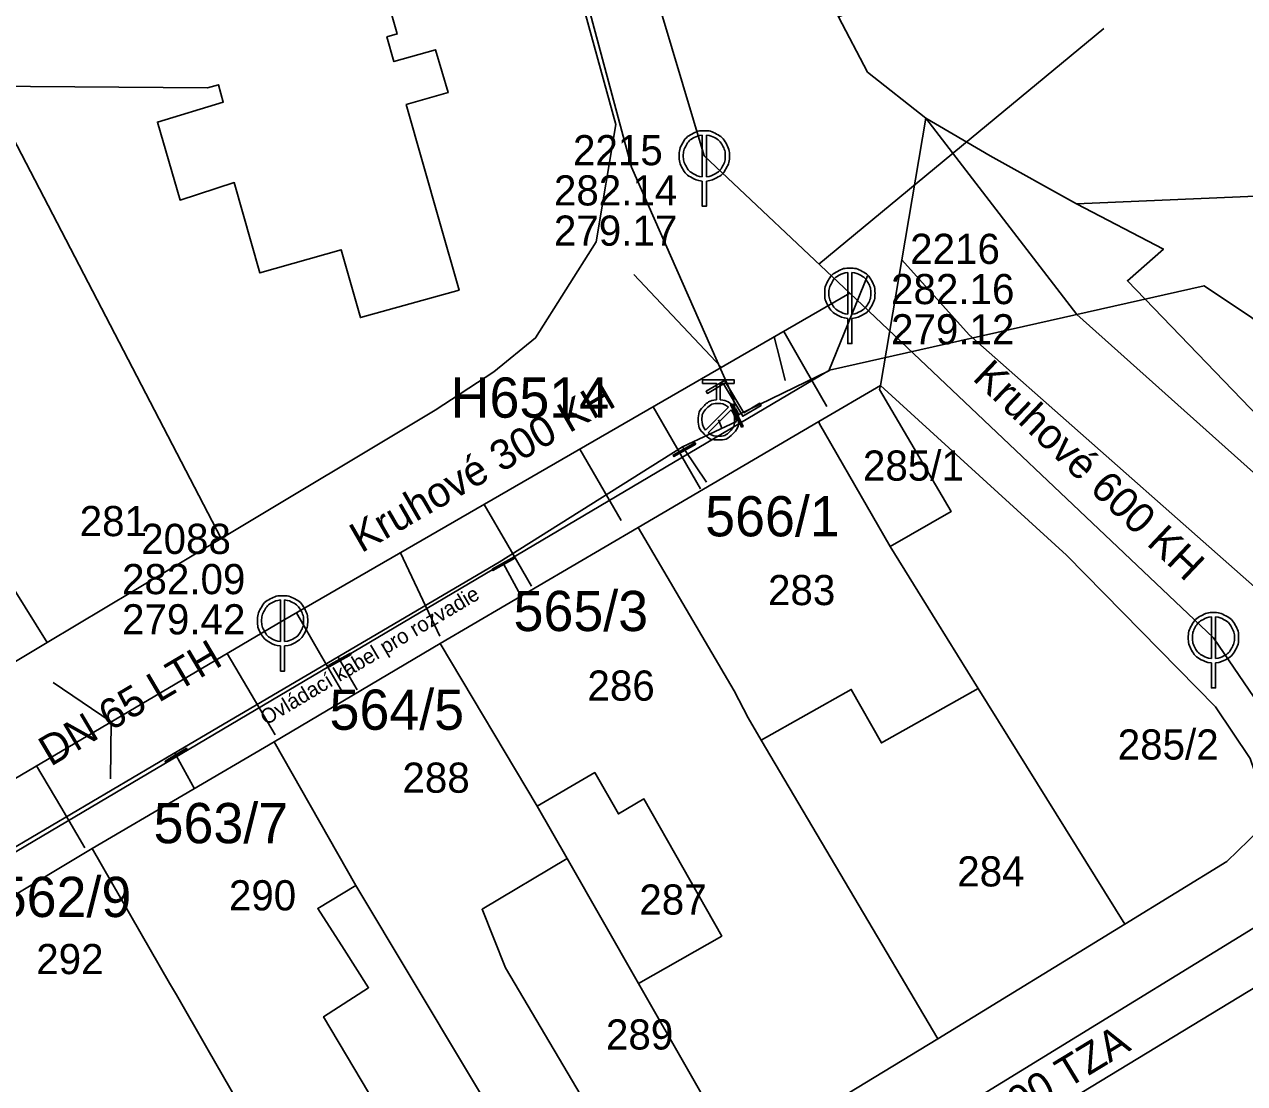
# Model space of a CAD drawing. Extents: x -571312 to -571060, y -1087128 to -1086933.
# Drawn here: x -571153.9 to -571093.3, y -1087034.1 to -1086981.5 of the extents above; entities that cross this region are included whole.
import ezdxf

# ---------------------------------------------------------------- set-up
doc = ezdxf.new("R2010")
doc.units = 0
for name, color, linetype in [('Adresní místo-text', 7, 'Continuous'), ('Armatura vodovodní', 7, 'Continuous'), ('Default', 7, 'Continuous'), ('Elektro NN - vedení', 7, 'Continuous'), ('Elektro VN_ VVN - popis', 7, 'Continuous'), ('Hydrant', 7, 'Continuous'), ('Kanalizační přípojka', 7, 'Continuous'), ('Kanalizační stoka', 7, 'Continuous'), ('Kanalizační šachta', 7, 'Continuous'), ('Označení hydrantu', 7, 'Continuous'), ('Parcela-polygon', 7, 'Continuous'), ('Parcela-text', 7, 'Continuous'), ('Popis kmenové stoky', 7, 'Continuous'), ('Popis šachty', 7, 'Continuous'), ('Vodovodní přípojka', 7, 'Continuous'), ('Vodovodní řad', 7, 'Continuous'), ('Změna materiálu', 7, 'Continuous'), ('Řad vodovodní popis', 7, 'Continuous')]:
    doc.layers.add(name, color=color, linetype=linetype)

msp = doc.modelspace()

# ---------------------------------------------------------------- linework, layer by layer
at = {"layer": 'Armatura vodovodní'}
for points in [[(-571118.748, -1087000.329), (-571118.201, -1087001.453), (-571118.272, -1087001.488), (-571118.818, -1087000.363), (-571118.748, -1087000.329)], [(-571120.555, -1087002.333), (-571121.642, -1087002.95), (-571121.681, -1087002.882), (-571120.594, -1087002.265), (-571120.555, -1087002.333)], [(-571129.55, -1087008.003), (-571130.637, -1087008.62), (-571130.676, -1087008.552), (-571129.588, -1087007.935), (-571129.55, -1087008.003)], [(-571137.685, -1087012.803), (-571138.78, -1087013.406), (-571138.818, -1087013.337), (-571137.723, -1087012.734), (-571137.685, -1087012.803)], [(-571145.837, -1087017.527), (-571146.906, -1087018.174), (-571146.946, -1087018.107), (-571145.877, -1087017.46), (-571145.837, -1087017.527)]]:
    msp.add_lwpolyline(points, dxfattribs=at)
at = {"layer": 'Default'}
for points in [[(-571120.233, -1086989.248), (-571120.491, -1086989.23), (-571120.753, -1086989.084), (-571121.05, -1086988.92), (-571121.215, -1086988.623), (-571121.38, -1086988.325), (-571121.38, -1086988), (-571121.38, -1086987.673), (-571121.212, -1086987.373), (-571121.043, -1086987.072), (-571120.745, -1086986.911), (-571120.447, -1086986.75), (-571120.13, -1086986.75), (-571119.815, -1086986.75), (-571119.516, -1086986.911), (-571119.217, -1086987.072), (-571119.048, -1086987.373), (-571118.88, -1086987.673), (-571118.88, -1086988), (-571118.88, -1086988.325), (-571119.045, -1086988.623), (-571119.21, -1086988.92), (-571119.507, -1086989.084), (-571119.769, -1086989.23), (-571120.027, -1086989.248)], [(-571120.233, -1086986.962), (-571120.43, -1086986.979), (-571120.645, -1086987.094), (-571120.894, -1086987.229), (-571121.033, -1086987.479), (-571121.172, -1086987.729), (-571121.172, -1086988), (-571121.172, -1086988.271), (-571121.036, -1086988.518), (-571120.899, -1086988.764), (-571120.65, -1086988.901), (-571120.438, -1086989.021), (-571120.233, -1086989.035)], [(-571120.027, -1086989.035), (-571119.822, -1086989.021), (-571119.608, -1086988.901), (-571119.361, -1086988.764), (-571119.224, -1086988.518), (-571119.088, -1086988.271), (-571119.088, -1086988), (-571119.088, -1086987.729), (-571119.228, -1086987.479), (-571119.368, -1086987.229), (-571119.617, -1086987.094), (-571119.83, -1086986.979), (-571120.027, -1086986.962)], [(-571112.993, -1086996.078), (-571113.251, -1086996.06), (-571113.513, -1086995.914), (-571113.81, -1086995.75), (-571113.975, -1086995.453), (-571114.14, -1086995.155), (-571114.14, -1086994.83), (-571114.14, -1086994.503), (-571113.972, -1086994.203), (-571113.803, -1086993.902), (-571113.505, -1086993.741), (-571113.207, -1086993.58), (-571112.89, -1086993.58), (-571112.575, -1086993.58), (-571112.276, -1086993.741), (-571111.977, -1086993.902), (-571111.808, -1086994.203), (-571111.64, -1086994.503), (-571111.64, -1086994.83), (-571111.64, -1086995.155), (-571111.805, -1086995.453), (-571111.97, -1086995.75), (-571112.267, -1086995.914), (-571112.529, -1086996.06), (-571112.787, -1086996.078)], [(-571112.993, -1086993.792), (-571113.19, -1086993.809), (-571113.405, -1086993.924), (-571113.654, -1086994.059), (-571113.793, -1086994.309), (-571113.932, -1086994.559), (-571113.932, -1086994.83), (-571113.932, -1086995.101), (-571113.796, -1086995.348), (-571113.659, -1086995.594), (-571113.41, -1086995.731), (-571113.198, -1086995.851), (-571112.993, -1086995.865)], [(-571112.787, -1086995.865), (-571112.582, -1086995.851), (-571112.368, -1086995.731), (-571112.121, -1086995.594), (-571111.984, -1086995.348), (-571111.848, -1086995.101), (-571111.848, -1086994.83), (-571111.848, -1086994.559), (-571111.988, -1086994.309), (-571112.128, -1086994.059), (-571112.377, -1086993.924), (-571112.59, -1086993.809), (-571112.787, -1086993.792)], [(-571119.336, -1087000.132), (-571118.978, -1087000.161), (-571118.72, -1087000.421), (-571118.429, -1087000.714), (-571118.429, -1087001.13), (-571118.429, -1087001.544), (-571118.722, -1087001.836), (-571119.015, -1087002.128), (-571119.431, -1087002.128), (-571119.844, -1087002.128), (-571120.137, -1087001.836), (-571120.429, -1087001.544), (-571120.429, -1087001.13), (-571120.429, -1087000.714), (-571120.138, -1087000.421), (-571119.881, -1087000.159), (-571119.523, -1087000.132)], [(-571118.924, -1087000.489), (-571119.14, -1087000.314), (-571119.431, -1087000.314), (-571119.769, -1087000.314), (-571120.007, -1087000.551), (-571120.244, -1087000.788), (-571120.244, -1087001.126), (-571120.244, -1087001.417), (-571120.068, -1087001.634)], [(-571119.935, -1087001.767), (-571119.72, -1087001.939), (-571119.431, -1087001.939), (-571119.095, -1087001.939), (-571118.857, -1087001.701), (-571118.619, -1087001.464), (-571118.619, -1087001.126), (-571118.619, -1087000.837), (-571118.791, -1087000.622)], [(-571141.203, -1087012.368), (-571141.461, -1087012.35), (-571141.723, -1087012.204), (-571142.02, -1087012.04), (-571142.185, -1087011.743), (-571142.35, -1087011.445), (-571142.35, -1087011.12), (-571142.35, -1087010.793), (-571142.182, -1087010.493), (-571142.013, -1087010.192), (-571141.715, -1087010.031), (-571141.417, -1087009.87), (-571141.1, -1087009.87), (-571140.785, -1087009.87), (-571140.486, -1087010.031), (-571140.187, -1087010.192), (-571140.018, -1087010.493), (-571139.85, -1087010.793), (-571139.85, -1087011.12), (-571139.85, -1087011.445), (-571140.015, -1087011.743), (-571140.18, -1087012.04), (-571140.477, -1087012.204), (-571140.739, -1087012.35), (-571140.997, -1087012.368)], [(-571141.203, -1087010.082), (-571141.4, -1087010.099), (-571141.615, -1087010.214), (-571141.864, -1087010.349), (-571142.003, -1087010.599), (-571142.142, -1087010.849), (-571142.142, -1087011.12), (-571142.142, -1087011.391), (-571142.006, -1087011.638), (-571141.869, -1087011.884), (-571141.62, -1087012.021), (-571141.408, -1087012.141), (-571141.203, -1087012.155)], [(-571140.997, -1087012.155), (-571140.792, -1087012.141), (-571140.578, -1087012.021), (-571140.331, -1087011.884), (-571140.194, -1087011.638), (-571140.058, -1087011.391), (-571140.058, -1087011.12), (-571140.058, -1087010.849), (-571140.198, -1087010.599), (-571140.338, -1087010.349), (-571140.587, -1087010.214), (-571140.8, -1087010.099), (-571140.997, -1087010.082)], [(-571094.913, -1087013.208), (-571095.171, -1087013.19), (-571095.433, -1087013.044), (-571095.73, -1087012.88), (-571095.895, -1087012.583), (-571096.06, -1087012.285), (-571096.06, -1087011.96), (-571096.06, -1087011.633), (-571095.892, -1087011.333), (-571095.723, -1087011.032), (-571095.425, -1087010.871), (-571095.127, -1087010.71), (-571094.81, -1087010.71), (-571094.495, -1087010.71), (-571094.196, -1087010.871), (-571093.897, -1087011.032), (-571093.728, -1087011.333), (-571093.56, -1087011.633), (-571093.56, -1087011.96), (-571093.56, -1087012.285), (-571093.725, -1087012.583), (-571093.89, -1087012.88), (-571094.187, -1087013.044), (-571094.449, -1087013.19), (-571094.707, -1087013.208)], [(-571094.913, -1087010.922), (-571095.11, -1087010.939), (-571095.325, -1087011.054), (-571095.574, -1087011.189), (-571095.713, -1087011.439), (-571095.852, -1087011.689), (-571095.852, -1087011.96), (-571095.852, -1087012.231), (-571095.716, -1087012.478), (-571095.579, -1087012.724), (-571095.33, -1087012.861), (-571095.118, -1087012.981), (-571094.913, -1087012.995)], [(-571094.707, -1087012.995), (-571094.502, -1087012.981), (-571094.288, -1087012.861), (-571094.041, -1087012.724), (-571093.904, -1087012.478), (-571093.768, -1087012.231), (-571093.768, -1087011.96), (-571093.768, -1087011.689), (-571093.908, -1087011.439), (-571094.048, -1087011.189), (-571094.297, -1087011.054), (-571094.51, -1087010.939), (-571094.707, -1087010.922)]]:
    msp.add_open_spline(points, degree=3, dxfattribs=at)
at = {"layer": 'Elektro NN - vedení'}
msp.add_lwpolyline([(-571071.926, -1087014.396), (-571073.5, -1087015.707), (-571083.992, -1087003.116), (-571092.911, -1086996.034), (-571095.272, -1086994.46), (-571113.896, -1086998.657), (-571175.538, -1087035.118), (-571177.374, -1087030.659), (-571213.311, -1086976.361), (-571216.983, -1086969.541), (-571228.263, -1086944.884), (-571229.263, -1086941.883)], dxfattribs=at)
at = {"layer": 'Hydrant'}
for points in [[(-571119.523, -1087000.132), (-571119.523, -1086999.315), (-571120.211, -1086999.315), (-571120.211, -1086999.128), (-571118.648, -1086999.128), (-571118.648, -1086999.315), (-571119.336, -1086999.315), (-571119.336, -1087000.132)], [(-571120.068, -1087001.634), (-571118.924, -1087000.489)], [(-571118.791, -1087000.622), (-571119.935, -1087001.767)]]:
    msp.add_lwpolyline(points, dxfattribs=at)
at = {"layer": 'Kanalizační přípojka'}
for points in [[(-571100.26, -1086981.67), (-571107.346, -1086987.523), (-571114.431, -1086993.376)], [(-571123.64, -1086993.9), (-571121.46, -1086996.21), (-571119.28, -1086998.52)], [(-571114.031, -1087000.454), (-571115.106, -1086998.592), (-571116.181, -1086996.73)], [(-571116.1, -1086999.17), (-571116.378, -1086998.087), (-571116.657, -1086997.005)], [(-571120.326, -1087004.551), (-571121.501, -1087002.516), (-571122.676, -1087000.481)], [(-571124.263, -1087006.132), (-571125.288, -1087004.356), (-571126.313, -1087002.581)], [(-571128.726, -1087009.401), (-571129.901, -1087007.366), (-571131.076, -1087005.331)], [(-571133.275, -1087011.878), (-571134.253, -1087009.805), (-571135.232, -1087007.732)], [(-571138.107, -1087014.704), (-571139.257, -1087012.712), (-571140.407, -1087010.72)], [(-571141.468, -1087016.794), (-571142.662, -1087014.77), (-571143.856, -1087012.746)], [(-571152.5, -1087014.18), (-571149.617, -1087016.144)], [(-571149.65, -1087018.97), (-571149.617, -1087016.144)], [(-571150.93, -1087022.404), (-571152.13, -1087020.369), (-571153.331, -1087018.334)]]:
    msp.add_lwpolyline(points, dxfattribs=at)
at = {"layer": 'Kanalizační stoka'}
for points in [[(-571131.72, -1086949.28), (-571125.925, -1086968.64), (-571120.13, -1086988)], [(-571120.13, -1086988), (-571112.89, -1086994.83)], [(-571141.1, -1087011.12), (-571112.89, -1086994.83)], [(-571112.89, -1086994.83), (-571094.81, -1087011.96)], [(-571185.11, -1087037.08), (-571141.1, -1087011.12)], [(-571094.81, -1087011.96), (-571085.827, -1087025.142)], [(-571123.22, -1087047.86), (-571104.524, -1087036.501), (-571085.827, -1087025.142)]]:
    msp.add_lwpolyline(points, dxfattribs=at)
at = {"layer": 'Kanalizační šachta'}
for points in [[(-571120.233, -1086989.035), (-571120.233, -1086986.962)], [(-571120.027, -1086986.962), (-571120.027, -1086989.035)], [(-571120.027, -1086989.248), (-571120.027, -1086990.5), (-571120.233, -1086990.5), (-571120.233, -1086989.248)], [(-571112.993, -1086995.865), (-571112.993, -1086993.792)], [(-571112.787, -1086993.792), (-571112.787, -1086995.865)], [(-571112.787, -1086996.078), (-571112.787, -1086997.33), (-571112.993, -1086997.33), (-571112.993, -1086996.078)], [(-571141.203, -1087012.155), (-571141.203, -1087010.082)], [(-571140.997, -1087010.082), (-571140.997, -1087012.155)], [(-571094.913, -1087012.995), (-571094.913, -1087010.922)], [(-571094.707, -1087010.922), (-571094.707, -1087012.995)], [(-571140.997, -1087012.368), (-571140.997, -1087013.62), (-571141.203, -1087013.62), (-571141.203, -1087012.368)], [(-571094.707, -1087013.208), (-571094.707, -1087014.46), (-571094.913, -1087014.46), (-571094.913, -1087013.208)]]:
    msp.add_lwpolyline(points, dxfattribs=at)
at = {"layer": 'Parcela-polygon'}
for points in [[(-571122.956, -1086932.879), (-571124.19, -1086936.69), (-571140.74, -1086942.7), (-571140.64, -1086942.98), (-571137.75, -1086951.51), (-571135.94, -1086951.84), (-571132.79, -1086956.45), (-571124.52, -1086986.44), (-571125.5, -1086992.28), (-571128.52, -1086997.05), (-571130.59, -1086998.74), (-571133.51, -1087000.65), (-571144.15, -1087007.02), (-571152.8, -1087012.2), (-571165.57, -1087019.85)], [(-571159.39, -1087027.73), (-571150.57, -1087022.45), (-571141.52, -1087017.13), (-571133.26, -1087012.24), (-571123.41, -1087006.48), (-571114.43, -1087001.2), (-571111.37, -1086999.41), (-571110.31, -1086993.17), (-571109.12, -1086986.12), (-571112.01, -1086983.83), (-571113.46, -1086981.09), (-571119.61, -1086959.25), (-571120.15, -1086956.91), (-571120.27, -1086954.47), (-571119.98, -1086952.15), (-571118.5, -1086950.05), (-571116.6, -1086948.51), (-571111.4, -1086944.73), (-571102.09, -1086938.18), (-571099.58, -1086936.57), (-571098.526, -1086935.725)], [(-571095.268, -1086942.132), (-571099.58, -1086936.57), (-571102.09, -1086938.18), (-571111.4, -1086944.73), (-571095.29, -1086963.14), (-571093.62, -1086968.75), (-571094.58, -1086969.01), (-571094.04, -1086970.97), (-571095.08, -1086971.25), (-571094.86, -1086972.05), (-571095.79, -1086972.31), (-571095.15, -1086974.62), (-571094.93, -1086975.43), (-571109.82, -1086979.67), (-571113.46, -1086981.09), (-571112.01, -1086983.83), (-571109.12, -1086986.12), (-571105.91, -1086988), (-571101.62, -1086990.38), (-571071.391, -1086989.088)], [(-571137.22, -1086975.55), (-571135.4, -1086981.93), (-571135.91, -1086982.08), (-571135.56, -1086983.31), (-571133.5, -1086982.72), (-571132.87, -1086984.85), (-571134.95, -1086985.44), (-571133.29, -1086991.27), (-571132.32, -1086994.67), (-571137.23, -1086996.04), (-571138.19, -1086992.67), (-571142.23, -1086993.82), (-571143.5, -1086989.33), (-571146.2, -1086990.2), (-571147.32, -1086986.32), (-571144.05, -1086985.32), (-571144.29, -1086984.46), (-571144.84, -1086984.62), (-571155.86, -1086984.54), (-571144.15, -1087007.02), (-571133.51, -1087000.65), (-571130.59, -1086998.74), (-571128.52, -1086997.05), (-571125.5, -1086992.28), (-571124.52, -1086986.44), (-571132.79, -1086956.45)], [(-571155.86, -1086984.54), (-571144.84, -1086984.62), (-571144.29, -1086984.46), (-571144.05, -1086985.32), (-571147.32, -1086986.32), (-571146.2, -1086990.2), (-571143.5, -1086989.33), (-571142.23, -1086993.82), (-571138.19, -1086992.67), (-571137.23, -1086996.04), (-571132.32, -1086994.67), (-571133.29, -1086991.27), (-571134.95, -1086985.44), (-571132.87, -1086984.85), (-571133.5, -1086982.72), (-571135.56, -1086983.31), (-571135.91, -1086982.08), (-571135.4, -1086981.93), (-571137.22, -1086975.55)], [(-571069.833, -1087030.003), (-571086.38, -1087009.5), (-571101.6, -1086995.89), (-571109.12, -1086986.12), (-571110.31, -1086993.17), (-571106.96, -1086996.89), (-571089.5, -1087012.31), (-571087.4, -1087014.88), (-571071.845, -1087033.911)], [(-571068.289, -1087027.004), (-571072.47, -1087022.57), (-571082.95, -1087010.95), (-571099.09, -1086994.21), (-571097.3, -1086992.63), (-571101.62, -1086990.38), (-571105.91, -1086988), (-571109.12, -1086986.12), (-571101.6, -1086995.89), (-571086.38, -1087009.5), (-571069.833, -1087030.003)], [(-571071.391, -1086989.088), (-571101.62, -1086990.38), (-571097.3, -1086992.63), (-571099.09, -1086994.21), (-571082.95, -1087010.95), (-571072.47, -1087022.57), (-571070.77, -1087021.28), (-571061.853, -1087014.506)], [(-571238.048, -1087115.573), (-571084.13, -1087021.07), (-571088.23, -1087015.62), (-571087.4, -1087014.88), (-571089.5, -1087012.31), (-571106.96, -1086996.89), (-571110.31, -1086993.17), (-571111.37, -1086999.41), (-571102.11, -1087007.86), (-571094.7, -1087015.4), (-571092.99, -1087017.97), (-571091.96, -1087020.97), (-571094.14, -1087023.09), (-571099.22, -1087026.2), (-571108.52, -1087031.9), (-571118.39, -1087037.91), (-571122.75, -1087040.66), (-571126.3, -1087042.9), (-571130.43, -1087045.33), (-571135.47, -1087048.29), (-571143.89, -1087053.63), (-571152.72, -1087058.97), (-571161.7, -1087064.52)], [(-571100.979, -1087051.983), (-571102.73, -1087043.67), (-571081.09, -1087028.01), (-571079.74, -1087027.03), (-571084.13, -1087021.07), (-571238.048, -1087115.573)]]:
    msp.add_lwpolyline(points, dxfattribs=at)
for points in [[(-571144.15, -1087007.02), (-571155.86, -1086984.54), (-571166.67, -1086989.97), (-571152.8, -1087012.2)], [(-571179.74, -1086996.54), (-571179.19, -1086997.45), (-571175.25, -1087003.94), (-571172.31, -1087008.78), (-571167.11, -1087017.33), (-571165.57, -1087019.85), (-571152.8, -1087012.2), (-571166.67, -1086989.97)], [(-571111.37, -1086999.41), (-571114.43, -1087001.2), (-571114.4, -1087001.33), (-571110.89, -1087007.43), (-571107.85, -1087005.68), (-571111.41, -1086999.61)], [(-571091.96, -1087020.97), (-571092.99, -1087017.97), (-571094.7, -1087015.4), (-571102.11, -1087007.86), (-571111.37, -1086999.41), (-571111.41, -1086999.61), (-571107.85, -1087005.68), (-571110.89, -1087007.43), (-571108.56, -1087011.17), (-571106.51, -1087014.48), (-571099.22, -1087026.2), (-571094.14, -1087023.09)], [(-571114.43, -1087001.2), (-571123.41, -1087006.48), (-571118.65, -1087014.61), (-571117.95, -1087015.94), (-571117.3, -1087017.06), (-571112.82, -1087014.53), (-571111.32, -1087017.19), (-571106.78, -1087014.63), (-571106.51, -1087014.48), (-571108.56, -1087011.17), (-571110.89, -1087007.43), (-571114.4, -1087001.33)], [(-571123.41, -1087006.48), (-571133.26, -1087012.24), (-571128.44, -1087020.34), (-571125.58, -1087018.67), (-571124.4, -1087020.72), (-571123.13, -1087019.98), (-571119.26, -1087026.8), (-571123.4, -1087029.16), (-571118.39, -1087037.91), (-571108.52, -1087031.9), (-571117.3, -1087017.06), (-571117.95, -1087015.94), (-571118.65, -1087014.61)], [(-571133.26, -1087012.24), (-571141.52, -1087017.13), (-571137.45, -1087024.29), (-571126.3, -1087042.9), (-571122.75, -1087040.66), (-571130.01, -1087028.38), (-571131.18, -1087025.46), (-571126.95, -1087022.94), (-571128.44, -1087020.34)], [(-571099.22, -1087026.2), (-571106.51, -1087014.48), (-571106.78, -1087014.63), (-571111.32, -1087017.19), (-571112.82, -1087014.53), (-571117.3, -1087017.06), (-571108.52, -1087031.9)], [(-571141.52, -1087017.13), (-571150.57, -1087022.45), (-571146.72, -1087029.14), (-571146.38, -1087029.72), (-571144.87, -1087032.36), (-571143.27, -1087035.13), (-571140.54, -1087039.85), (-571135.47, -1087048.29), (-571130.43, -1087045.33), (-571139.06, -1087030.81), (-571136.82, -1087029.37), (-571138.04, -1087027.46), (-571139.35, -1087025.42), (-571137.45, -1087024.29)], [(-571123.13, -1087019.98), (-571124.4, -1087020.72), (-571125.58, -1087018.67), (-571128.44, -1087020.34), (-571126.95, -1087022.94), (-571123.4, -1087029.16), (-571119.26, -1087026.8)], [(-571150.57, -1087022.45), (-571159.39, -1087027.73), (-571155.35, -1087034.47), (-571153.13, -1087038.18), (-571151.82, -1087040.36), (-571143.27, -1087035.13), (-571144.87, -1087032.36), (-571146.38, -1087029.72), (-571146.72, -1087029.14)], [(-571126.95, -1087022.94), (-571131.18, -1087025.46), (-571130.01, -1087028.38), (-571122.75, -1087040.66), (-571118.39, -1087037.91), (-571123.4, -1087029.16)], [(-571137.45, -1087024.29), (-571139.35, -1087025.42), (-571138.04, -1087027.46), (-571136.82, -1087029.37), (-571139.06, -1087030.81), (-571130.43, -1087045.33), (-571126.3, -1087042.9)]]:
    msp.add_lwpolyline(points, close=True, dxfattribs=at)
at = {"layer": 'Vodovodní přípojka'}
msp.add_line((-571130.113, -1087008.278), (-571129.376, -1087009.666), dxfattribs=at)
for points in [[(-571118.555, -1087000.931), (-571118.51, -1087000.908), (-571113.943, -1086998.689), (-571112.012, -1086993.967)], [(-571121.213, -1087002.468), (-571121.118, -1087002.608), (-571120.017, -1087004.223)], [(-571138.341, -1087012.915), (-571138.251, -1087013.07), (-571137.391, -1087014.552)], [(-571146.459, -1087017.695), (-571146.392, -1087017.817), (-571145.485, -1087019.469)]]:
    msp.add_lwpolyline(points, dxfattribs=at)
at = {"layer": 'Vodovodní řad'}
msp.add_line((-571119.429, -1087001.128), (-571119.253, -1087001.545), dxfattribs=at)
for points in [[(-571118.52, -1087001.2), (-571118.67, -1087000.053), (-571123.745, -1086988.554), (-571132.766, -1086954.96), (-571134.366, -1086951.47), (-571139.458, -1086950.161), (-571144.547, -1086950.9), (-571169.366, -1086958.786), (-571197.91, -1086970.492), (-571213.143, -1086976.341), (-571239.84, -1086984.572), (-571249.273, -1086987.925), (-571267.719, -1086980.097), (-571298.302, -1086956.821), (-571302.312, -1086953.213), (-571303.56, -1086950.89)], [(-571118.52, -1087001.2), (-571121.219, -1087002.471), (-571130.326, -1087008.201), (-571146.537, -1087017.741), (-571155.651, -1087023.106), (-571186.289, -1087039.932), (-571190.097, -1087043.426), (-571196.691, -1087047.158), (-571208.123, -1087053.111), (-571216.72, -1087058.494), (-571222.809, -1087062.06), (-571226.167, -1087064.027), (-571239.701, -1087072.13)]]:
    msp.add_lwpolyline(points, dxfattribs=at)
at = {"layer": 'Změna materiálu'}
msp.add_lwpolyline([(-571118.171, -1087000.775), (-571117.364, -1087000.297), (-571117.301, -1087000.405), (-571118.216, -1087000.946), (-571119.17, -1086999.332), (-571119.977, -1086999.809), (-571120.04, -1086999.702), (-571119.126, -1086999.161), (-571118.171, -1087000.775)], dxfattribs=at)

# ---------------------------------------------------------------- texts
at = {"layer": 'Adresní místo-text'}
for s, p in [('566/1', (-571120.085, -1087006.92)), ('565/3', (-571129.615, -1087011.63)), ('564/5', (-571138.765, -1087016.54)), ('563/7', (-571147.515, -1087022.18)), ('562/9', (-571155.315, -1087025.85))]:
    msp.add_text(s, height=2, dxfattribs=at).set_placement(p)
at = {"layer": 'Elektro VN_ VVN - popis'}
msp.add_text('Ovládací kabel pro rozvadie', height=0.75, rotation=30.67728, dxfattribs=at).set_placement((-571141.926, -1087016.335))
at = {"layer": 'Označení hydrantu'}
msp.add_text('H6514', height=2, dxfattribs=at).set_placement((-571132.742, -1087001.019))
at = {"layer": 'Parcela-text'}
for s, p in [('285/1', (-571112.24, -1087004.15)), ('281', (-571151.19, -1087006.91)), ('283', (-571116.96, -1087010.34)), ('286', (-571125.94, -1087015.09)), ('285/2', (-571099.57, -1087018.02)), ('288', (-571135.14, -1087019.67)), ('284', (-571107.55, -1087024.33)), ('290', (-571143.77, -1087025.52)), ('287', (-571123.36, -1087025.73)), ('292', (-571153.35, -1087028.69)), ('289', (-571125.02, -1087032.44))]:
    msp.add_text(s, height=1.5, dxfattribs=at).set_placement(p)
at = {"layer": 'Popis kmenové stoky'}
for s, rotation, p in [('Kruhové 600 KH', 316.54552, (-571106.843, -1086999.103)), ('Kruhové 300 KH', 30.00449, (-571137.182, -1087007.77)), ('Kruhové 800 TZA', 31.28064, (-571112.274, -1087040.593))]:
    msp.add_text(s, height=1.5, rotation=rotation, dxfattribs=at).set_placement(p)
at = {"layer": 'Popis šachty'}
for s, p in [('2215', (-571126.657, -1086988.465)), ('282.14', (-571127.606, -1086990.465)), ('279.17', (-571127.606, -1086992.465)), ('2216', (-571109.892, -1086993.372)), ('282.16', (-571110.842, -1086995.372)), ('279.12', (-571110.842, -1086997.372)), ('2088', (-571148.133, -1087007.795)), ('282.09', (-571149.083, -1087009.795)), ('279.42', (-571149.083, -1087011.795))]:
    msp.add_text(s, height=1.5, dxfattribs=at).set_placement(p)
at = {"layer": 'Řad vodovodní popis'}
msp.add_text('DN 65 LTH', height=1.5, rotation=30.60311, dxfattribs=at).set_placement((-571152.635, -1087018.39))

doc.saveas('drawing.dxf')
